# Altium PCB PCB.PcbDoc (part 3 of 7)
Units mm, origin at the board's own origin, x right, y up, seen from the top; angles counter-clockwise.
Board outline 243.2 x 142.8 mm, 4 copper layers (Top Layer, Layer 1, Layer 2, Bottom Layer), stack 0.603 mm thick; 451 components, 380 nets, 2276 pads, 1520 vias.
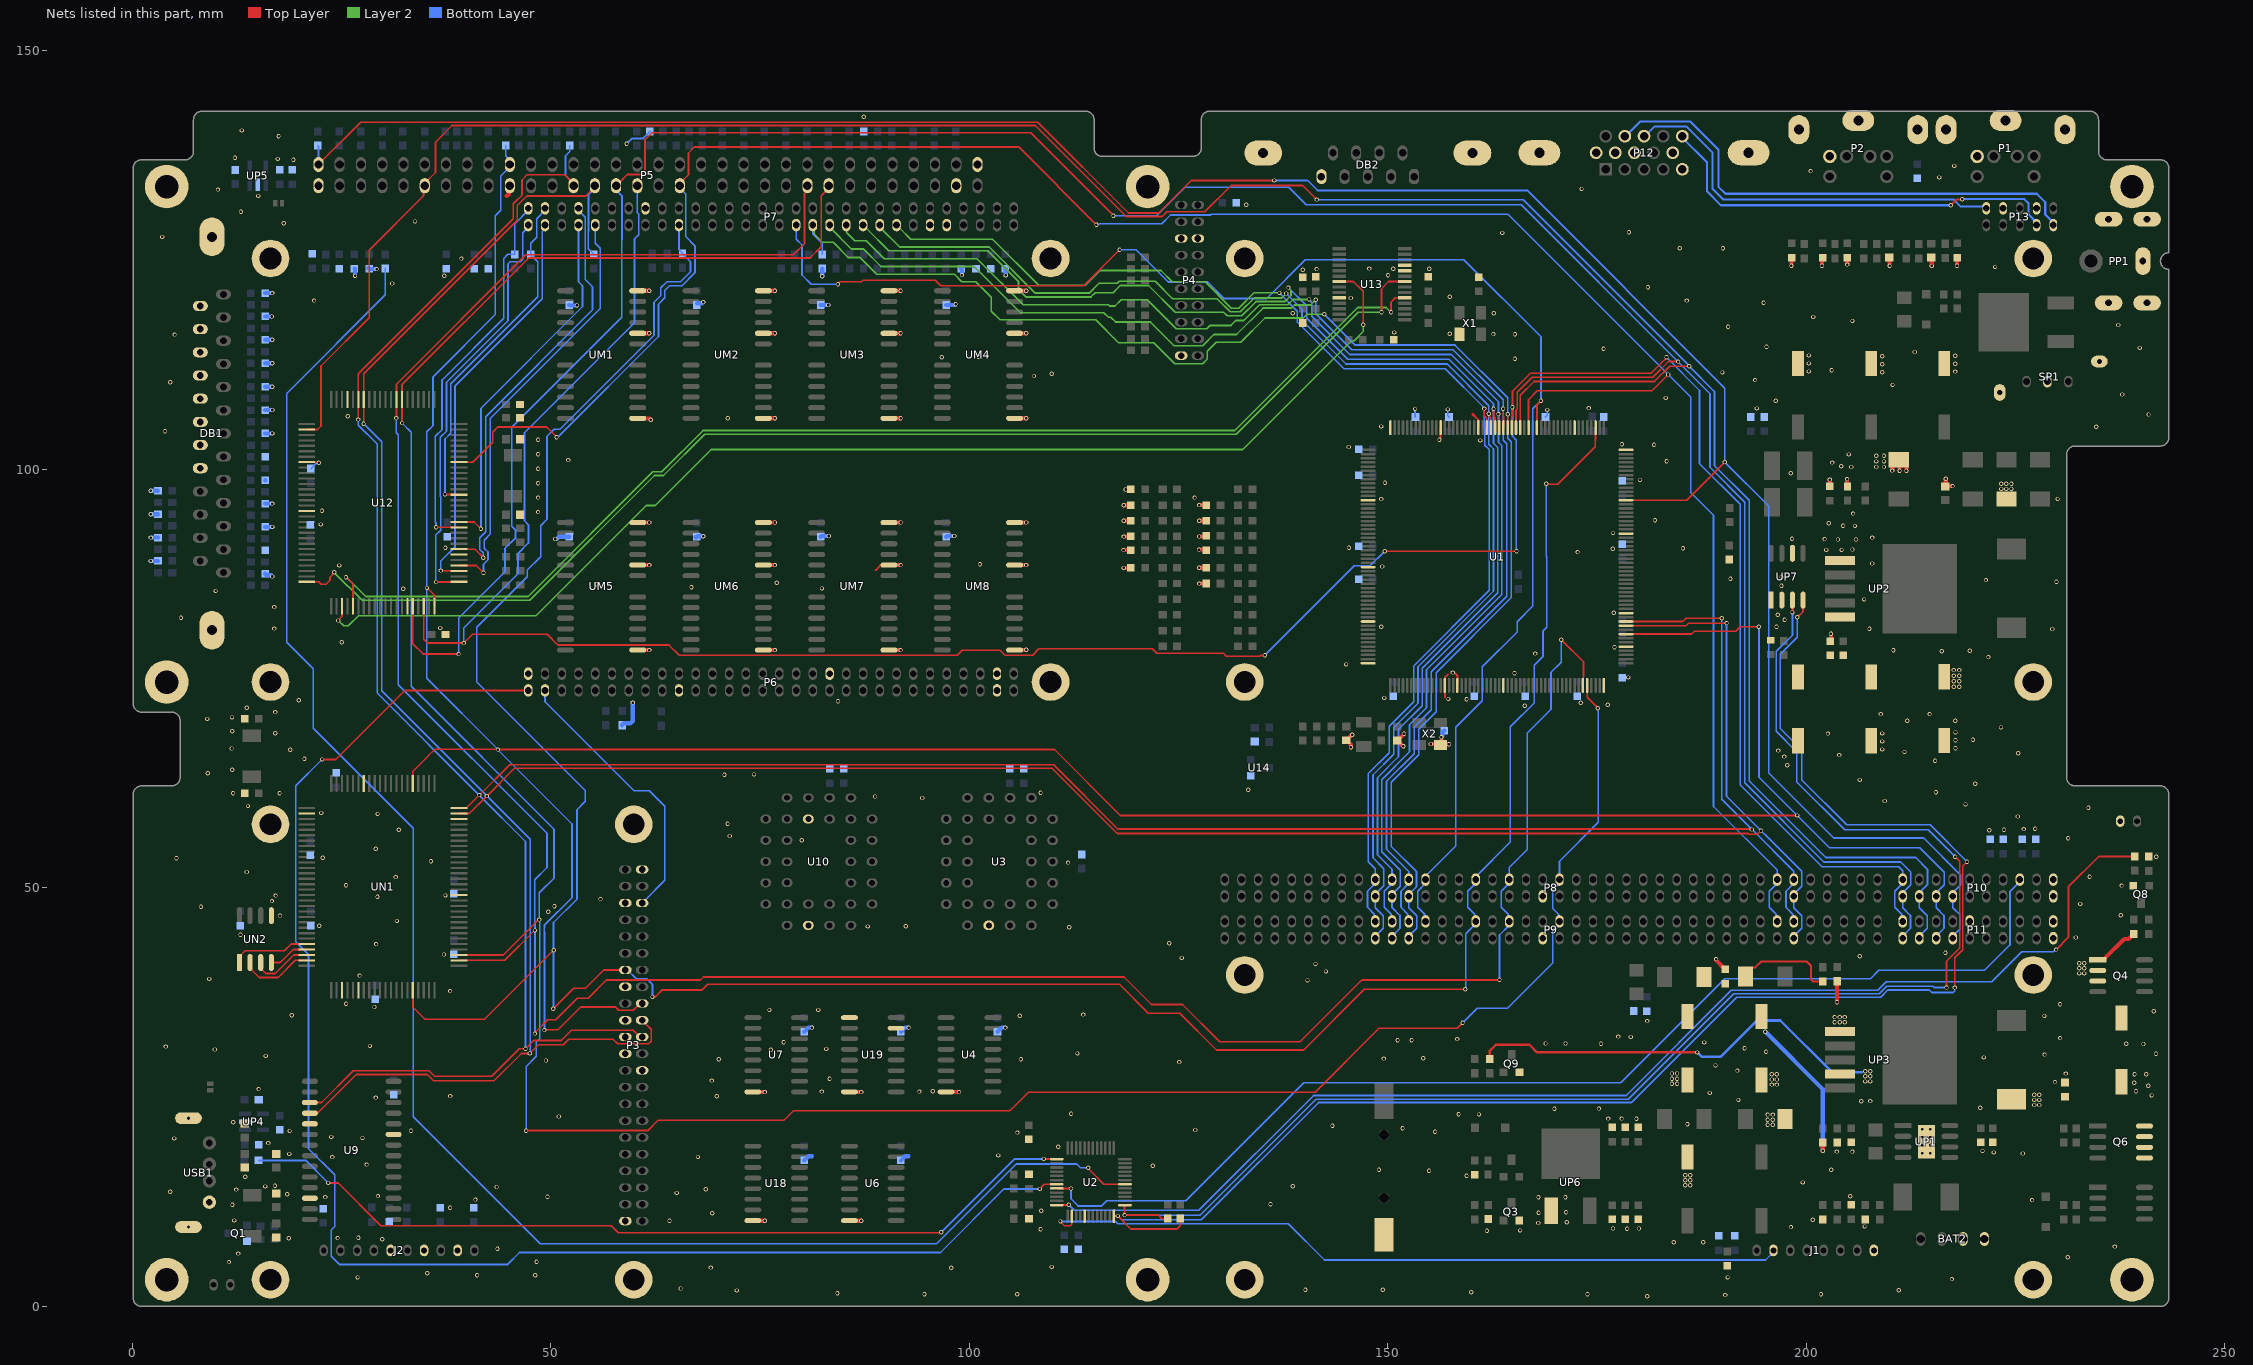
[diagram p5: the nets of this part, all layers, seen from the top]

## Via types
v1: diameter 0.508, hole 0.305, Top Layer to Bottom Layer, tented both sides, 1451 vias
v2: diameter 0.508, hole 0.3, Top Layer to Bottom Layer, 67 vias
v3: diameter 1.2, hole 1.2, Top Layer to Bottom Layer, 2 vias

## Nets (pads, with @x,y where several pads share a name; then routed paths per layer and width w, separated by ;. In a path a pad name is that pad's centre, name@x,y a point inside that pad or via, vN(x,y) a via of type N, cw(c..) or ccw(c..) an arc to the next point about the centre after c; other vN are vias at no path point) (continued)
DACK3#: P5.29 P10.20 P11.20 U1.22 U12.96 | length 333
  Top Layer w0.203: U12.96@33.501,83.654 33.501,79.191 34.728,77.964 38.954,77.964 v1(38.975,77.943) ; P5.29@57.79,133.9 57.79,133.93 58.25,134.391 58.281,134.391 59.125,135.235 60.705,135.235 61.251,135.781 61.251,139.411 62.08,140.241 107.34,140.241 117.205,130.376 v1(117.205,130.316) ; U1.22@165.305,104.994 165.305,107.064 165.441,107.201 165.441,109.206 167.241,111.006 181.635,111.006 183.522,112.893 v1(184.669,112.893)
  Bottom Layer w0.203: v1(38.975,77.943) 38.975,82.261 43.852,87.138 43.857,87.138 44.512,87.792 44.512,90.567 45.782,91.837 45.782,92.751 45.312,93.221 45.312,105.029 58.464,118.181 58.464,127.45 58.486,127.471 58.486,132.704 57.79,133.4 P5.29@57.79,133.9 ; v1(117.205,130.316) 117.207,130.318 122.363,130.318 125.767,133.721 138.136,133.721 140.242,131.616 165.921,131.616 184.644,112.893 v1(184.669,112.893) ; v1@184.656,112.881 188.477,109.06 188.477,100.248 192.643,96.082 192.643,62.552 202.088,53.107 211.258,53.107 212.457,51.908 212.457,50.384 211.5,49.427 P10.20@211.5,49 211.5,47.638 212.437,46.701 212.437,45.187 211.5,44.25 P11.20@211.5,44
DACK5#: P7.35 P8.58 P9.58 R22.2 U1.24 | length 177
  Top Layer w0.203: U1.24@164.305,104.994 164.314,105.003 164.314,106.584 v1(164.324,106.594)
  Layer 2 w0.203: P7.35@81.3,129.2 81.432,129.068 81.432,128.145 82.434,127.143 83.73,127.143 85.558,125.314 86.946,125.314 88.938,123.322 98.218,123.322 99.097,122.444 100.748,122.444 102.602,120.589 102.602,118.92 103.65,117.872 115.094,117.872 117.812,115.154 122.033,115.154 124.547,112.639 127.875,112.639 128.435,113.2 128.435,114.14 129.5,115.205 132.421,115.205 135.317,118.1 139.889,118.1 140.341,118.552 v1(142.404,118.552)
  Bottom Layer w0.203: P7.35@81.3,129.2 81.3,128.15 82.425,127.025 R22.2@82.425,125.7 ; v1(142.404,118.552) 146.097,114.859 158.014,114.859 164.324,108.549 v1(164.324,106.594) 164.324,103.722 164.754,103.292 164.754,84.701 155.764,75.711 155.764,71.043 153.677,68.956 153.677,65.919 150.405,62.647 150.405,54.956 153.427,51.933 153.427,50.177 152.5,49.25 P8.58@152.5,49 152.5,47.638 153.437,46.701 153.437,45.187 P9.58@152.5,44.25
DACK6#: P7.39 P8.60 P9.60 U1.26 | length 165.6
  Top Layer w0.203: v1(163.206,106.619) 163.206,106.537 163.305,106.439 U1.26@163.305,104.994
  Layer 2 w0.203: P7.39@85.3,129.2 85.361,129.139 85.361,128.28 86.315,127.326 87.687,127.326 89.827,125.185 100.915,125.185 106.434,119.666 116.606,119.666 116.75,119.523 117.387,119.523 118.124,120.259 121.253,120.259 124.717,116.795 128.373,116.795 128.789,117.211 131.253,117.211 131.837,117.795 132.777,117.795 134.657,119.675 138.035,119.675 138.67,120.31 v1(140.575,120.31)
  Bottom Layer w0.203: v1(140.575,120.31) 140.888,119.997 140.888,118.315 145.461,113.742 157.551,113.742 163.206,108.086 v1(163.206,106.619) 163.206,103.265 163.611,102.86 163.611,85.07 154.621,76.079 154.621,71.517 152.589,69.485 152.589,66.259 149.262,62.931 149.262,54.346 151.471,52.136 151.471,50.221 150.5,49.25 P8.60@150.5,49 150.5,47.638 151.437,46.701 151.437,45.187 150.5,44.25 P9.60@150.5,44
DACK7#: P7.43 P8.62 P9.62 U1.28 | length 159.1
  Top Layer w0.203: v1(162.063,106.645) 162.122,106.586 162.122,106.339 162.305,106.156 U1.28@162.305,104.994
  Layer 2 w0.203: P7.43@89.3,129.2 89.3,128.95 91.667,126.583 102.374,126.583 107.886,121.071 114.31,121.071 115.48,122.24 117.664,122.24 117.893,122.469 122.211,122.469 124.275,120.405 129.583,120.405 131.151,118.837 132.371,118.837 134.022,120.488 137.324,120.488 v1(137.857,121.021)
  Bottom Layer w0.203: v1(137.857,121.021) 139.745,119.133 139.745,117.841 144.987,112.599 157.077,112.599 162.063,107.613 v1(162.063,106.645) 162.063,103.013 162.626,102.45 162.626,85.478 153.591,76.443 153.591,72.062 150.709,69.18 150.709,65.979 148.22,63.49 148.22,53.61 149.516,52.314 149.516,50.266 P8.62@148.5,49.25 ; P9.62@148.5,44 148.5,44.25 149.437,45.187 149.437,46.701 148.5,47.638 P8.62@148.5,49.25 ; P8.62@148.5,49 P8.62@148.5,49.25
DCD1#: U12.85 U13.19 | length 147.2
  Top Layer w0.203: v1(25.513,87.133) 25.577,87.133 26.351,86.36 U12.85@26.351,83.654 ; v1(150.379,118.786) 150.379,119.984 150.895,120.5 U13.19@152,120.5
  Layer 2 w0.203: v1(25.513,87.133) 25.568,87.133 27.875,84.826 47.281,84.826 62.19,99.736 63.257,99.736 68.185,104.664 131.705,104.664 146.387,119.345 149.82,119.345 v1(150.379,118.786)
DCDC12V: C26.1 CP6.1 CP8.1 DP7.K DP10.A R88.1 R114.1 | length 30.1
  Top Layer w0.254: DP7.K@192.721,39.436 192.721,39.736 193.494,40.509 193.896,40.509 194.601,41.214 200.036,41.214 200.544,40.706 200.544,39.081 200.798,38.827 R88.1@201.967,38.827
  Top Layer w0.508: v1(201.941,18.608) 201.941,19.548 R114.1@201.967,19.574
  Bottom Layer w0.508: v1(195.083,32.832) 201.941,25.974 v1(201.941,18.608)
DDCSCK: P12.12 P13.9 | length 60.7
  Bottom Layer w0.254: P12.12@178.31,139.72 180.16,141.57 186.142,141.57 189.478,138.234 189.478,133.789 190.333,132.934 227.519,132.934 228.535,131.918 228.535,130.465 229.5,129.5 P13.9@229.5,129.2
DDCSDA: P12.15 P13.7 | length 50.3
  Top Layer w0.254: v1(217.257,131.562) 217.969,132.273 v1(218.629,132.273)
  Bottom Layer w0.254: P12.15@185.18,139.72 185.18,139.637 188.124,136.693 188.124,133.228 189.783,131.569 217.251,131.569 v1(217.257,131.562) ; v1(218.629,132.273) 218.654,132.299 226.046,132.299 226.528,131.816 226.528,130.472 227.5,129.5 P13.7@227.5,129.2
DENSEL#: P7.1 U12.1 | length 50.7
  Top Layer w0.203: v1(36.282,86.553) 36.285,86.551 38.997,86.551 U12.1@39.026,86.579
  Bottom Layer w0.203: v1(36.282,86.553) 36.257,86.579 36.257,92.167 36.841,92.751 36.841,96.736 36.79,96.787 36.79,103.837 37.519,104.566 37.519,110.422 44.868,117.77 44.868,124.552 45.122,124.806 46.341,124.806 46.62,125.085 46.62,128.27 47.3,128.95 P7.1@47.3,129.2
DIR#: P7.8 U12.7 | length 51.6
  Top Layer w0.203: U12.7@39.026,90.479 40.942,90.479 41.921,89.5 v1(41.921,89.448)
  Bottom Layer w0.203: v1(41.921,89.448) 41.921,90.033 41.515,90.44 41.515,91.862 42.201,92.548 42.201,106.308 54.977,119.084 54.977,121.809 54.089,122.697 54.089,128.601 54.105,128.617 54.105,130.145 53.3,130.95 P7.8@53.3,131.2
DRQ0: P7.33 P8.55 P9.55 U1.17 | length 184.6
  Top Layer w0.203: v1(84.288,122.139) 84.568,122.418 87.108,122.418 87.286,122.596 95.922,122.596 96.558,121.959 113.646,121.959 117.939,126.252 v1(117.945,126.252) ; U1.17@167.805,104.994 167.805,107.738 168.285,108.218 v1(168.288,108.218)
  Bottom Layer w0.203: P7.33@79.3,129.2 79.3,127.514 79.996,126.818 79.996,123.231 81.088,122.139 v1(84.288,122.139) ; v1(117.945,126.252) 117.948,126.255 119.898,126.255 123.748,122.405 128.472,122.405 130.463,120.414 135.497,120.414 140.145,125.062 159.064,125.062 168.286,115.84 v1(168.288,108.218) ; P9.55@154.384,46.116 154.384,46.865 153.558,47.691 153.558,49.622 P8.55@154.5,50.564 ; P8.55@154.5,51 154.5,51.406 158.103,55.009 158.103,69.182 161.27,72.349 161.27,76.413 165.441,80.584 165.441,81.807 167.321,83.687 167.321,107.254 168.285,108.218 v1(168.288,108.218)
DRQ1: P5.35 P8.13 P9.13 U1.19 U12.23 | length 279.6
  Top Layer w0.203: U12.23@39.026,100.879 40.651,100.879 43.039,103.267 43.039,104.46 43.648,105.07 49.49,105.07 50.683,103.878 v1(50.683,103.852) ; P5.35@65.41,133.9 65.41,134.2 66.432,135.222 66.432,137.811 67.158,138.536 105.89,138.536 v1(115.175,129.251) ; U1.19@166.805,104.994 166.805,108.338 167.854,109.388 181.545,109.388 v1(183.501,111.344)
  Bottom Layer w0.203: v1(50.683,103.852) 50.765,103.852 50.892,103.979 50.94,103.979 62.851,115.89 62.851,119.751 63.597,120.498 63.597,121.387 64.172,121.961 65.67,121.961 67.207,123.498 67.207,126.724 66.105,127.826 66.105,132.905 65.41,133.6 P5.35@65.41,133.9 ; v1(115.175,129.251) 115.233,129.309 115.484,129.309 115.528,129.352 122.973,129.352 124.025,130.405 128.826,130.405 128.914,130.493 139.777,130.493 164.348,130.493 183.499,111.342 186.193,108.649 186.193,97.244 188.904,94.533 188.904,59.737 196.5,52.141 P8.13@196.5,51 ; P9.13@196.5,46 196.384,46.116 196.384,46.865 195.558,47.691 195.558,49.622 P8.13@196.5,50.564
DRQ2: P5.11 P10.18 P11.18 U1.21 U12.52 | length 320.2
  Top Layer w0.203: U12.52@20.826,104.779 22.123,104.779 22.541,105.197 22.541,112.369 28.281,118.109 28.281,126.203 34.774,132.695 34.774,133.744 P5.11@34.93,133.9 34.93,134.2 36.206,135.476 36.206,139.106 38.193,141.093 107.879,141.093 118.751,130.222 123.029,130.222 123.593,130.786 128.14,130.786 131.278,133.924 139.813,133.924 v1(141.489,132.248) ; U1.21@165.805,104.994 165.805,107.025 165.822,107.043 165.822,108.88 167.448,110.506 181.842,110.506 183.67,112.334 185.99,112.334 v1(185.991,112.336)
  Bottom Layer w0.203: v1(141.489,132.248) 141.511,132.227 166.174,132.227 185.991,112.409 v1(185.991,112.336) 189.011,109.316 189.011,100.469 193.177,96.303 193.177,62.774 202.31,53.641 213.054,53.641 214.457,52.238 214.457,50.384 213.5,49.427 P10.18@213.5,49 213.5,47.638 214.437,46.701 214.437,45.187 213.5,44.25 P11.18@213.5,44
DRQ3: P5.31 P10.19 P11.19 U1.23 U12.98 | length 332.8
  Top Layer w0.203: U12.98@34.801,83.654 34.801,79.729 35.266,79.264 v1(39.584,79.264) 40.626,80.305 49.55,80.305 50.826,79.029 64.102,79.029 65.321,77.81 98.536,77.81 99.136,78.41 103.657,78.41 104.258,77.81 107.553,77.81 108.306,78.562 121.845,78.562 122.379,78.029 130.353,78.029 130.704,77.678 134.645,77.678 134.747,77.78 135.276,77.78 v1(135.306,77.81) ; v1(149.617,90.236) v1(165.365,90.236) ; U1.23@164.805,104.994 164.805,106.285 164.883,106.363 v1(164.883,107.432) 164.883,109.354 167.034,111.506 181.427,111.506 183.287,113.365 v1(183.287,113.4)
  Bottom Layer w0.203: v1(39.584,79.264) 39.584,81.067 46.081,87.563 46.081,89.979 47.314,91.212 47.314,93.385 46.844,93.855 46.844,104.394 59.996,117.546 59.996,127.564 60.486,128.054 60.486,130.519 60.33,130.675 P5.31@60.33,133.9 ; v1(135.306,77.81) 145.98,88.484 147.865,88.484 v1(149.617,90.236) ; v1(164.883,107.432) 164.883,103.978 165.352,103.508 165.352,90.249 v1(165.365,90.236) ; v1(183.287,113.4) 183.287,113.386 187.235,109.439 187.235,100.703 192.111,95.826 192.111,62.296 201.858,52.55 211.027,52.55 211.5,52.077 P10.19@211.5,51 ; P11.19@211.384,46.116 211.384,46.865 210.558,47.691 210.558,49.622 P10.19@211.5,50.564
DRQ5: P7.37 P8.57 P9.57 U1.25 | length 166.8
  Top Layer w0.203: v1(163.765,107.254) 163.765,106.363 163.805,106.323 U1.25@163.805,104.994
  Layer 2 w0.203: P7.37@83.3,129.2 83.3,128.95 85.92,126.33 87.367,126.33 89.443,124.254 100.591,124.254 104.558,120.287 104.558,120.285 106.108,118.734 116.065,118.734 116.623,118.176 116.909,118.176 117.468,117.618 121.626,117.618 124.449,114.795 127.883,114.795 129.207,116.119 131.913,116.119 135.088,119.294 138.492,119.294 138.848,119.65 140.753,119.65 v1(141.388,120.285)
  Bottom Layer w0.203: v1(141.388,120.285) 141.388,118.605 145.692,114.301 157.782,114.301 163.765,108.318 v1(163.765,107.254) 163.765,103.495 164.183,103.078 164.183,84.833 155.193,75.843 155.193,71.28 153.148,69.235 153.148,66.056 149.833,62.741 149.833,54.638 152.5,51.971 P8.57@152.5,51 ; P9.57@152.384,46.116 152.384,46.865 151.558,47.691 151.558,49.622 P8.57@152.5,50.564
DRQ6: P7.41 P8.59 P9.59 U1.27 | length 161.8
  Top Layer w0.203: v1(162.622,107.254) 162.622,106.413 162.805,106.231 U1.27@162.805,104.994
  Layer 2 w0.203: P7.41@87.3,129.2 87.3,129.166 87.668,128.798 87.702,128.798 90.383,126.117 102.185,126.117 105.878,122.424 105.878,121.466 106.73,120.615 114.534,120.615 115.042,121.123 117.183,121.123 117.577,121.517 117.577,121.531 118.033,121.986 121.398,121.986 124.589,118.795 130.355,118.795 130.796,118.354 132.548,118.354 134.25,120.056 137.682,120.056 138.416,120.79 138.416,121.345 138.111,121.65 v1(138.111,121.732)
  Bottom Layer w0.203: v1(138.111,121.732) 140.304,119.54 140.304,118.073 145.219,113.158 157.309,113.158 162.622,107.844 v1(162.622,107.254) 162.622,103.14 163.138,102.624 163.138,85.266 154.103,76.231 154.103,71.786 151.268,68.951 151.268,65.7 148.754,63.185 148.754,53.959 150.5,52.213 P8.59@150.5,51 ; P9.59@150.384,46.116 150.384,46.865 149.558,47.691 149.558,49.622 P8.59@150.5,50.564
DRQ7: P7.45 P8.61 P9.61 U1.29 | length 153.7
  Top Layer w0.203: v1(161.504,107.28) 161.504,106.413 161.692,106.225 161.692,106.193 161.805,106.081 U1.29@161.805,104.994
  Layer 2 w0.203: P7.45@91.3,129.2 91.3,129.166 91.668,128.798 91.702,128.798 92.985,127.515 102.76,127.515 108.272,122.003 113.871,122.003 115.632,123.764 122.886,123.764 124.236,122.414 128.158,122.414 131.304,119.269 132.167,119.269 133.996,121.097 v1(137.044,121.097)
  Bottom Layer w0.203: v1(137.044,121.097) 137.044,121.044 139.186,118.902 139.186,117.61 144.756,112.04 156.846,112.04 161.363,107.523 161.363,107.503 161.504,107.362 v1(161.504,107.28) 161.504,105.012 161.582,104.935 161.582,102.912 162.114,102.38 162.114,85.557 153.079,76.522 153.079,72.261 150.151,69.332 150.151,66.157 147.661,63.668 147.661,53.127 148.5,52.288 P8.61@148.5,51 ; P9.61@148.5,46 148.384,46.116 148.384,46.865 147.558,47.691 147.558,49.622 P8.61@148.5,50.564
DS0#: P7.9 U12.4 | length 51.3
  Top Layer w0.203: U12.4@39.026,88.529 41.063,88.529 v1(41.947,87.646)
  Bottom Layer w0.203: v1(41.947,87.646) 41.947,88.663 42.48,89.197 42.48,90.132 42.023,90.589 42.023,91.557 42.759,92.294 42.759,106.086 55.912,119.238 55.912,126.411 55.3,127.023 P7.9@55.3,129.2
DS1#: P7.3 U12.3 | length 48.6
  Top Layer w0.203: v1(36.841,87.925) 36.864,87.902 39.003,87.902 U12.3@39.026,87.879
  Bottom Layer w0.203: v1(36.841,87.925) 36.841,89.068 38.553,90.78 38.553,109.99 48.957,120.394 48.957,128.433 49.3,128.776 P7.3@49.3,129.2
DSKCHG#: P7.4 R137.1 U12.17 | length 41.5
  Top Layer w0.203: v1(37.349,97.018) 37.369,96.999 39.006,96.999 U12.17@39.026,96.979
  Bottom Layer w0.203: v1(37.349,97.018) 37.349,103.648 38.036,104.335 38.036,110.227 48.424,120.615 48.424,124.814 47.576,125.662 R137.1@47.576,125.7 47.576,127.032 48.297,127.752 48.297,129.947 49.3,130.95 P7.4@49.3,131.2
DSR1#: U12.80 U13.22 | length 151
  Top Layer w0.203: U12.80@20.826,86.579 22.274,86.579 22.578,86.274 23.128,86.274 23.601,86.747 23.601,87.128 24.131,87.658 v1(24.131,87.733) ; v1(149.236,118.786) 149.236,121.605 150.081,122.45 U13.22@152,122.45
  Layer 2 w0.203: v1(24.131,87.733) 24.131,87.679 27.442,84.369 47.47,84.369 62.38,99.279 63.447,99.279 68.374,104.206 131.895,104.206 146.474,118.786 v1(149.236,118.786)
DTR1#: U12.83 U13.7 | length 147.3
  Top Layer w0.203: v1(24.598,81.956) 24.598,82.007 25.051,82.459 U12.83@25.051,83.654 ; U13.7@144.2,122.45 145.877,122.45 147.052,121.275 v1(147.052,117.28)
  Layer 2 w0.203: v1(24.598,81.956) 25.233,81.321 25.792,81.321 27.01,82.539 48.228,82.539 61.387,95.697 62.479,95.697 69.159,102.378 132.652,102.378 145.657,115.382 145.96,115.382 147.052,116.475 v1(147.052,117.28)
EECS: UN1.76 UN2.1 | length 9.4
  Top Layer w0.203: UN2.1@12.79,41.1 12.79,41.811 13.463,42.484 18.147,42.484 18.962,43.3 UN1.76@20.826,43.3
EED5: UN1.79 UN2.2 | length 8.8
  Top Layer w0.203: UN2.2@14.06,41.1 14.06,40.389 15.139,39.309 17.436,39.309 19.476,41.35 UN1.79@20.826,41.35
EED6: UN1.78 UN2.3 | length 7.4
  Top Layer w0.203: UN2.3@15.33,41.1 15.33,40.399 15.95,39.779 17.067,39.779 19.288,42 UN1.78@20.826,42
EED7: UN1.77 UN2.4 | length 4.9
  Top Layer w0.203: UN2.4@16.6,41.1 17.651,41.1 19.201,42.65 UN1.77@20.826,42.65
EN_MIO: R144.1 U12.58 | length 2.7
  Top Layer w0.203: U12.58@20.826,100.879 20.854,100.85 22.211,100.85 v1(22.26,100.801)
  Bottom Layer w0.203: R144.1@21.3,100.1 21.338,100.1 21.983,100.744 22.203,100.744 v1(22.26,100.801)
ERR_FLP: P6.1 U2.7 | length 181.8
  Top Layer w0.203: v2(22.657,65.354) 24.308,65.354 32.554,73.6 P6.1@47.3,73.6 ; v1(108.407,14.046) 108.964,14.603 U2.7@110.431,14.603
  Bottom Layer w0.203: v2(22.657,65.354) 19.533,62.23 19.533,43.561 21.031,42.062 21.031,18.872 24.181,15.723 24.181,9.55 23.774,9.144 23.774,6.02 24.79,5.004 44.806,5.004 46.253,6.452 96.545,6.452 104.14,14.046 v1(108.407,14.046)
ERR_ISA: R150.2 U2.30 | length 208.8
  Top Layer w0.203: v1(114.197,16.562) 114.197,16.486 116.066,14.617 118.567,14.617 U2.30@118.581,14.603
  Bottom Layer w0.203: R150.2@30.226,124.005 30.226,120.853 18.44,109.068 18.44,79.348 21.615,76.173 21.615,69.088 33.553,57.15 33.553,22.682 48.743,7.493 96.063,7.493 105.585,17.015 112.827,17.015 113.28,16.562 v1(114.197,16.562)
ERR_USB: R151.2 U2.1 | length 102.6
  Top Layer w0.203: v1(23.393,14.757) 24.587,14.757 29.693,9.652 57.226,9.652 58.064,8.814 96.593,8.814 v1(96.646,8.866) ; v1(108.89,17.628) 108.902,17.615 110.419,17.615 U2.1@110.431,17.603
  Bottom Layer w0.203: R151.2@15.086,17.45 20.701,17.45 v1(23.393,14.757) ; v1(96.646,8.866) 96.648,8.866 105.41,17.628 v1(108.89,17.628)
FAN_SW: R102.1 U2.12 | length 150.1
  Top Layer w0.203: U2.12@110.431,12.103 110.45,12.121 111.842,12.121 v1(111.862,12.141) ; v1(229.83,42.637) 231.304,44.11 231.304,50.13 234.936,53.762 R102.1@239.228,53.762
  Bottom Layer w0.203: v1(111.862,12.141) 112.522,11.481 127.406,11.481 141.122,25.197 178.46,25.197 191.033,37.77 208.534,37.77 209.55,38.786 222.148,38.786 225.73,42.367 229.508,42.367 229.778,42.637 v1(229.83,42.637)
GND: BAT1.2 BAT2.1 BAT2.2 C1.1 C2.2 C3.2 C4.1 C5.2 C6.2 C7.2 C8.2 C9.2 C10.2 C11.1 C12.1 C13.2 C14.2 C15.2 C16.2 C17.2 C18.2 C19.2 C20.2 C21.2 C23.2 C24.2 C25.2 C26.2 C27.2 C28.2 C29.2 C30.2 C31.2 C32.2 C33.1 C34.1 C35.1 C36.2 C37.2 C38.2 C39.2 C40.2 C41.2 C42.2 C43.2 C44.2 C45.2 C46.2 C47.2 C48.2 C49.2 C50.2 C51.2 C52.2 C53.2 C54.2 C55.2 C56.2 C57.2 C58.2 C59.2 C60.2 C61.2 C62.2 C63.2 C64.2 C65.2 C66.2 C67.2 C68.2 C69.2 C70.2 C71.2 C72.2 C73.2 C74.2 C75.2 C76.2 C77.1 C78.1 C79.2 C80.2 C81.2 C82.2 C83.2 C84.2 C85.2 C90.2 C91.2 C99.2 C100.2 C101.2 C102.2 C103.2 C104.2 C105.2 C106.2 C107.2 C108.2 C109.2 C110.2 C111.2 C112.2 C113.2 C114.2 C115.2 C116.2 C117.1 C118.1 C119.2 C120.2 C121.2 C122.2 C126.2 C130.2 C131.2 C132.2 C133.2 C134.2 C135.2 C136.2 C137.2 C138.2 C139.2 C140.2 C141.2 C142.2 C143.2 C144.2 C145.2 C146.2 C147.2 C148.2 C149.2 CM1.2 CM2.2 CM3.2 CM4.2 CM5.2 CM6.2 CM7.2 CM8.2 CM9.2 CM10.2 CM11.2 CM12.2 CN1.2 CN2.2 CN3.2 CN4.2 CN5.2 CP1.1 CP2.2 CP3.2 CP4.2 CP5.2 CP6.2 CP8.2 CP9.2 CP10.2 CP11.2 CP12.1 DB1.0 DB1.18 DB1.19 DB1.20 DB1.21 DB1.22 DB1.23 DB1.24 DB1.25 DB2.0 DB2.5 DP6.A DP8.K J1.1 J2.2 J2.4 J2.6 LED2.2 M1.1 M2.1 M3.1 M4.1 M5.1 M6.1 M7.1 P1.3 P1.7 P2.3 P2.7 P3.2 P3.19 P3.22 P3.24 P3.26 P3.30 P3.40 P3.43 P4.2 P4.15 P4.16 P5.1 P5.19 P5.61 P5.64 P6.2 P6.19 P6.38 P6.57 P6.58 P7.16 P7.49 P7.51 P8.42 P9.42 P10.1 P10.2 P11.1 P11.2 P12.0 P12.5 P12.6 P12.7 P12.8 P12.10 P13.4 P13.8 PP1.2 PP1.3 PP2.1 Q1.E Q3.E Q8.E Q9.E R7.1 R22.1 R23.1 R24.1 R25.1 R26.2 R89.2 R97.2 R103.2 R111.2 R113.1 R115.1 R116.1 R117.1 R145.2 R146.2 R147.2 RT1.2 SP1.0 SP1.2 T1.1 T2.1 T3.1 T4.1 T5.1 T6.1 T7.1 T8.1 T11.1 T12.1 T13.1 T14.1 T15.1 T16.1 T17.1 T18.1 U1.8 U1.31 U1.40 U1.52 U1.65 U1.81 U1.94 U1.104 U1.118 U1.121 U1.132 U1.156 U1.161 U1.169 U1.188 U1.208 U2.17 U3.16 U4.8 U6.8 U7.8 U9.5 U9.12 U9.23 U10.3 U10.16 U12.6 U12.47 U12.67 U12.95 U13.10 U13.24 U13.25 U14.1 U18.8 U19.1 U19.8 U19.15 UM1.13 UM1.20 UM1.24 UM2.13 UM2.20 UM2.24 UM3.13 UM3.20 UM3.24 UM4.13 UM4.20 UM4.24 UM5.13 UM5.20 UM5.24 UM6.13 UM6.20 UM6.24 UM7.13 UM7.20 UM7.24 UM8.13 UM8.20 UM8.24 UN1.14 UN1.28 UN1.44 UN1.52 UN1.83 UN1.86 UN2.5 UP1.0 UP2.1 UP3.1 UP4.2 UP5.2 UP6.1 UP7.1 UP7.2 UP7.6 USB1.0 USB1.GND X1.2 X2.2 | length 127
  Top Layer w0.254: 88.81,87.976 89.345,88.511 90.324,88.511 UM7.20@90.392,88.579 ; v1(156.159,103.546) 156.159,103.615 156.305,103.76 U1.40@156.305,104.994 ; 156.805,72.787 U1.118@156.805,74.206 156.813,74.215 156.813,75.144 157.161,75.491 ; 158.05,75.631 158.305,75.377 U1.121@158.305,74.206 ; 160.108,106.619 160.796,105.932 160.796,105.003 U1.31@160.805,104.994
  Top Layer w0.508: 44.729,132.664 44.958,132.892 44.958,133.768 P5.19@45.09,133.9 ; UM5.13@60.377,78.421 v1(61.759,78.421) ; UM5.20@60.377,88.581 v1(61.759,88.581) ; UM5.24@60.377,93.661 v1(61.759,93.661) ; UM1.13@60.377,106.111 60.398,106.09 61.78,106.09 v1(61.925,105.945) ; UM1.20@60.377,116.271 v1(61.759,116.271) ; UM1.24@60.377,121.351 v1(61.759,121.351) ; U7.8@74.128,25.63 74.138,25.62 75.549,25.62 v1(75.551,25.619) ; U18.8@74.138,10.253 75.549,10.253 v1(75.551,10.252) ; UM6.13@75.385,78.421 v1(76.767,78.421) ; UM6.20@75.385,88.581 v1(76.767,88.581) ; UM6.24@75.385,93.661 v1(76.767,93.661) ; UM2.13@75.385,106.111 v1(76.767,106.111) ; UM2.20@75.385,116.271 75.388,116.268 v1(76.77,116.268) ; UM2.24@75.385,121.351 v1(76.767,121.351) ; U6.8@85.67,10.263 85.68,10.253 87.091,10.253 v1(87.093,10.252) ; U19.8@85.67,25.63 85.68,25.62 87.091,25.62 v1(87.093,25.619) ; UM7.13@90.392,78.419 v1(91.775,78.421) ; UM7.20@90.392,88.579 v1(91.775,88.581) ; UM7.24@90.392,93.659 v1(91.775,93.661) ; UM3.13@90.394,106.111 v1(91.775,106.111) ; UM3.20@90.394,116.271 v1(91.775,116.271) ; UM3.24@90.394,121.351 v1(91.775,121.351) ; U4.8@97.212,25.63 97.222,25.62 98.755,25.62 v1(98.756,25.619) ; UM8.13@105.402,78.421 105.419,78.439 106.776,78.439 v1(106.783,78.446) ; UM8.20@105.402,88.581 v1(106.783,88.581) ; UM8.24@105.402,93.661 v1(106.783,93.661) ; UM4.13@105.402,106.111 v1(106.783,106.111) ; UM4.20@105.402,116.271 v1(106.783,116.271) ; UM4.24@105.402,121.351 v1(106.783,121.351) ; v1(118.415,90.373) 119.084,90.373 119.3,90.157 CM8.2@119.3,90.152 ; v1(118.453,88.233) 119.282,88.233 CM6.2@119.3,88.251 ; v1(118.453,91.986) 119.282,91.986 CM10.2@119.3,92.004 ; v1(118.453,93.861) 119.282,93.861 CM12.2@119.3,93.879 ; v1(118.453,95.736) 119.282,95.736 CM2.2@119.3,95.754 ; v1(118.664,97.609) 119.282,97.609 CM4.2@119.3,97.627 ; v1(127.432,90.424) 128.076,90.424 128.309,90.191 CM9.2@128.309,90.152 ; v1(127.462,86.368) 128.291,86.368 CM5.2@128.3,86.377 CM5.2@128.309,86.386 ; v1(127.462,88.243) 128.291,88.243 CM7.2@128.3,88.252 CM7.2@128.309,88.261 ; v1(127.462,91.993) 128.291,91.993 CM11.2@128.309,92.011 ; v1(127.462,93.868) 128.291,93.868 CM1.2@128.3,93.877 CM1.2@128.309,93.886 ; v1(127.462,95.743) 128.291,95.743 CM3.2@128.3,95.752 CM3.2@128.309,95.761 ; C3.2@145.013,67.655 145.051,67.655 145.579,67.127 v1(145.579,66.818) ; C3.2@145.068,67.667 145.068,67.672 145.687,68.291 v1(145.731,68.291) ; C4.1@151.113,67.605 151.151,67.605 151.837,66.919 v1(151.852,66.919) ; C4.1@151.24,67.718 151.926,68.404 v1(151.926,68.419) ; v1(155.129,67.199) 155.852,67.199 X2.2@155.981,67.069 ; X2.2@156.283,67.105 156.399,67.221 v1(156.399,68.011) ; X2.2@156.348,67.055 156.476,67.183 v1(157.302,67.183) ; v1(189.205,41.504) 189.205,41.376 C26.2@190.308,40.273 ; v1(198.207,124.323) C8.2@198.207,125.163 ; v1(201.865,124.323) C7.2@201.865,125.163 ; v1(202.779,98.796) 202.779,98.007 C28.2@202.805,97.982 ; C23.2@202.856,79.49 202.932,79.567 v1(202.932,80.381) ; v1(203.657,36.347) 203.657,38.849 R89.2@203.662,38.854 ; v1(204.862,98.847) 204.862,98.031 R111.2@204.912,97.982 ; v1(204.888,124.476) C18.2@204.888,125.316 ; v1(209.942,124.347) C6.2@209.942,125.187 ; v1(210.247,99.863) 210.247,100.512 210.893,101.158 DP6.A@211.034,101.158 ; v1(211.138,99.857) DP6.A@211.138,100.506 ; v1(211.951,99.857) DP6.A@211.951,100.506 ; v1(214.971,124.321) C5.2@214.971,125.161 ; C24.2@216.646,98.229 v1(216.646,98.879) ; C24.2@216.818,98.011 v1(217.467,98.011) ; v1(217.994,124.347) C17.2@217.994,125.187
  Bottom Layer w0.203: v1(153.246,107.229) 153.246,106.321 C41.2@153.3,106.267 ; v1(157.161,107.178) 157.161,106.406 C44.2@157.3,106.267 ; C59.2@168.831,106.267 169.032,106.469 v1(169.032,107.115)
  Bottom Layer w0.254: v1(59.041,138.903) 59.701,139.563 61.026,139.563 61.825,140.362 R25.1@61.825,140.4
  Bottom Layer w0.508: v1(2.196,89.068) C101.2@3.061,89.068 ; v1(2.196,91.862) C102.2@3.061,91.862 ; v1(2.196,94.656) C103.2@3.061,94.656 ; v1(2.196,97.45) C104.2@3.061,97.45 ; C100.2@15.859,87.544 16.055,87.348 16.59,87.348 v1(16.724,87.214) ; C110.2@15.859,93.132 v1(16.724,93.132) ; C111.2@15.859,95.926 v1(16.724,95.926) ; C112.2@15.859,98.72 C112.2@15.911,98.668 ; C114.2@15.859,104.308 v1(16.724,104.308) ; C115.2@15.859,107.102 v1(16.724,107.102) ; C116.2@15.859,109.896 v1(16.724,109.896) ; C105.2@15.859,112.69 v1(16.724,112.69) ; C106.2@15.859,115.484 v1(16.724,115.484) ; C107.2@15.859,118.278 v1(16.661,118.278) ; C108.2@15.859,121.072 v1(16.724,121.072) ; C35.1@26.554,123.993 26.605,123.942 v1(26.605,123.128) ; C34.1@28.154,124.055 28.267,123.942 v1(29.17,123.942) ; v1(50.529,91.695) 50.725,91.695 50.988,91.958 C149.2@52.199,91.958 ; C136.2@52.2,119.65 52.251,119.599 v1(53.121,119.599) ; R26.2@58.507,69.436 58.507,69.474 58.698,69.664 59.48,69.664 59.777,69.962 v1(59.777,72.152) ; C148.2@67.278,91.887 67.365,91.887 C148.2@67.437,91.959 67.508,92.03 v1(68.2,92.03) ; C135.2@67.492,119.846 68.061,119.846 v1(68.217,120.001) ; C40.2@80.275,17.442 80.783,17.95 81.187,17.95 ; C45.2@80.275,32.809 80.783,33.317 v1(81.187,33.317) ; C141.2@82.217,91.959 C141.2@82.217,91.959 82.306,92.049 v1(83.19,92.049) ; C144.2@82.217,119.65 v1(83.136,119.649) ; v1(82.414,123.079) R22.1@82.414,123.99 ; C36.2@91.817,17.442 92.325,17.95 92.726,17.95 92.729,17.948 ; C38.2@91.817,32.809 92.325,33.317 v1(92.728,33.317) ; C140.2@97.225,91.959 C140.2@97.225,91.959 97.315,92.049 v1(98.198,92.049) ; C142.2@97.225,119.65 98.257,119.649 v1(98.349,119.74) ; C139.2@99.024,123.99 99.107,123.906 v1(99.107,123.223) ; C39.2@103.359,32.809 103.867,33.317 104.268,33.317 v1(104.27,33.315) ; C20.2@104.289,123.99 104.331,123.948 v1(104.331,123.181) ; v1(156.399,68.011) 156.531,68.144 156.531,68.603 C62.2@156.727,68.799
  other v1: 180.986,1.209 190.308,1.362 94.626,1.463 105.726,1.463 173.849,1.463 201.738,1.463 84.238,1.565 159.955,1.692 72.198,1.921 211.034,1.946 140.143,1.997 149.389,1.997 65.492,2.149 217.384,3.267 26.91,3.47 190.587,3.47 41.185,3.724 48.144,3.724 35.216,3.978 109.83,4.724 11.532,5.309 231.227,5.883 12.649,6.325 236.841,7.153 184.161,7.674 187.666,7.674 29.845,8.026 18.68,8.144 161.835,9.033 165.797,9.083 178.573,9.287 176.897,9.312 179.996,9.312 198.157,9.49 206.945,9.566 167.956,9.972 171.36,10.049 64.172,10.252 12.178,10.277 200.747,10.353 69.266,11.125 168.007,11.192 171.283,11.242 37.959,11.801 11.949,12.157 135.977,12.208 226.96,12.716 40.981,12.766 167.981,13.046 171.207,13.046 23.049,13.071 49.592,13.097 205.243,13.173 29.335,13.194 18.502,13.401 65.049,13.564 4.532,13.706 12.406,13.96 68.515,13.995 43.51,14.275 15.886,14.341 138.619,14.367 17.029,14.417 185.512,14.47 186.122,14.47 199.579,14.824 185.512,15.08 186.122,15.08 13.473,15.484 159.396,15.611 185.512,15.69 186.122,15.69 154.926,16.221 148.931,16.348 202.983,16.348 121.918,16.826 27.977,16.957 23.887,17.846 67.562,17.868 103.452,18.045 18.731,18.227 225.843,18.278 213.854,18.292 214.814,18.292 222.388,18.405 203.618,18.507 205.497,18.507 221.042,18.583 213.854,19.253 214.814,19.253 16.242,19.523 4.99,20.082 27.494,20.132 213.854,20.213 214.814,20.213 23.76,20.259 155.637,20.869 18.782,20.971 33.285,20.996 126.975,21.082 213.854,21.174 214.814,21.174 151.751,21.301 143.369,21.606 195.367,21.709 195.977,21.709 185.787,21.758 12.051,22.012 195.367,22.319 195.977,22.319 179.691,22.418 176.338,22.444 177.913,22.444 50.95,22.694 195.367,22.929 195.977,22.929 169.901,23.622 175.209,23.647 191.883,24.679 29.069,24.958 37.971,25.132 69.81,25.121 241.235,25.212 188.454,25.517 82.372,25.679 94.031,25.679 239.381,25.72 15.073,25.974 240.854,26.355 195.85,26.51 196.46,26.51 183.937,26.612 184.547,26.612 239.178,26.736 229.703,26.813 69.226,26.99 195.85,27.12 196.46,27.12 83.298,27.219 183.937,27.221 184.547,27.221 195.85,27.729 196.46,27.729 239.203,27.752 240.6,27.752 183.937,27.831 184.547,27.831 230.973,27.829 191.756,28.184 189.14,28.794 125.067,29.196 49.403,29.388 70.064,29.53 106.158,29.53 149.504,29.616 221.194,29.759 15.937,29.937 228.459,30.089 241.768,30.191 112.903,30.226 195.185,30.419 76.276,30.673 9.841,30.699 82.891,30.775 192.619,30.851 3.999,31.054 28.383,31.131 240.27,31.359 238.212,31.385 175.463,31.394 168.834,31.42 171.221,31.42 77.798,31.558 230.313,32.07 179.005,32.197 177.532,32.248 203.366,33.971 203.975,33.971 204.585,33.971 180.986,34.102 203.366,34.58 203.975,34.58 204.585,34.58 228.433,34.712 19.036,34.788 241.514,35.271 76.11,35.433 81.952,35.433 28.916,35.779 230.313,36.109 25.527,36.17 37.959,37.684 140.397,38.954 9.181,39.132 27.138,39.538 142.595,40.033 141.351,40.919 125.386,41.646 206.386,41.849 37.222,42.053 29.12,43.297 123.887,43.399 232.167,44.085 12.914,44.415 111.924,45.304 87.856,45.401 92.403,45.427 22.327,45.491 31.609,46.066 17.639,46.701 237.552,46.726 49.682,47.168 8.19,47.768 50.419,47.803 232.726,48.098 16.674,48.428 55.928,48.678 29.272,48.936 17.105,49.088 37.4,49.114 237.654,50.282 31.456,51.298 13.676,51.908 111.785,53.035 35.673,53.178 5.269,53.559 22.744,53.61 241.794,53.737 29.069,54.676 79.982,55.714 71.374,56.21 221.855,56.886 31.812,56.962 223.607,56.962 225.97,57.039 227.316,57.064 71.106,57.658 225.258,58.537 29.297,58.842 22.566,58.969 233.691,59.579 13.803,59.807 219.01,59.985 209.358,60.391 94.372,60.747 88.733,60.925 12.025,61.306 17.588,61.306 108.509,61.366 215.479,61.433 133.325,61.747 220.178,62.449 206.386,62.906 70.737,63.511 74.267,63.562 9.003,63.693 11.924,64.125 197.725,64.659 215.378,65.192 20.56,65.446 197.344,65.7 203.922,65.878 225.309,66.081 211.72,66.259 196.633,66.411 18.858,66.513 209.049,66.556 11.848,66.665 217.812,66.683 209.049,67.508 217.812,67.635 219.899,67.707 202.576,68.443 209.049,68.461 17.08,68.494 217.812,68.588 11.924,68.723 223.252,69.18 212.05,69.993 217.791,69.993 8.952,70.196 11.898,70.374 208.875,70.78 214.717,70.78 17.055,71.009 13.676,71.542 166.363,71.771 176.262,71.898 173.037,72.128 84.3,72.3 19.863,72.441 159.396,72.533 157.237,72.59 149.566,72.71 178.726,75.149 165.125,75.667 157.745,75.733 145.006,76.712 221.753,77.587 216.165,78.273 219.518,78.349 210.399,78.4 177.075,78.771 25.005,79.365 229.373,80.94 207.529,80.965 16.942,80.991 36.79,81.065 149.211,81.194 196.429,81.194 197.395,82.032 5.802,82.286 196.582,82.642 176.998,82.87 16.942,83.556 206.894,84.471 9.943,85.487 32.371,85.741 82.383,85.791 66.788,85.918 197.014,86.096 55.434,86.299 76.999,86.477 229.881,86.579 221.448,86.782 190.918,86.934 197.014,87.112 149.312,88.408 24.7,88.535 101.256,88.671 207.859,88.763 172.667,90.131 202.373,90.389 204.202,90.389 205.497,90.44 176.871,90.516 185.253,90.592 37.4,90.643 145.35,90.643 203.77,91.633 205.929,91.633 202.17,91.684 198.284,91.735 207.859,91.862 176.897,92.421 205.802,93.259 204.38,93.284 22.49,93.437 202.678,93.564 181.901,93.945 205.573,94.732 48.474,94.91 22.643,95.062 149.211,96.459 230.008,96.485 48.474,96.637 126.898,96.647 48.474,98.364 149.643,98.415 180.123,98.745 198.118,99.554 48.474,100.092 205.345,100.295 208.347,100.293 209.261,100.293 204.151,100.396 203.084,100.828 208.347,100.959 209.261,100.959 183.298,100.981 52.086,101.119 208.347,101.626 209.261,101.626 205.065,101.793 48.474,101.819 145.325,102.682 181.799,102.962 177.964,103.013 161.023,103.471 48.474,103.546 3.897,104.562 234.631,105.095 149.211,105.146 71.143,106.133 25.741,106.365 240.879,106.569 194.056,107.29 174.001,107.331 196.328,108.22 183.208,108.546 237.73,108.956 210.298,110.099 4.532,110.429 193.864,110.683 107.707,111.166 109.841,111.445 189.964,111.594 209.075,111.616 217.787,111.692 200.286,111.717 203.008,111.852 209.075,112.568 217.787,112.644 200.286,112.67 165.176,113.233 96.709,113.401 101.092,113.462 209.075,113.521 217.787,113.597 200.286,113.622 212.939,114.036 175.77,114.436 239.813,114.519 195.236,114.671 5.04,116.119 165.176,116.154 150.759,116.373 190.638,117.059 237.273,117.262 205.497,117.745 200.824,118.227 138.619,118.659 194.88,119.929 21.703,120.183 185.711,120.183 145.553,120.488 181.062,121.758 31.05,122.215 37.246,123.131 150.024,123.206 139.838,123.866 141.483,123.936 150.633,123.968 154.951,123.993 222.541,124.196 39.316,125.201 184.872,126.431 190.029,126.431 3.567,127.778 163.65,128.256 178.802,128.336 18.096,129.429 33.768,129.632 12.965,130.8 133.082,131.638 15.048,132.68 10.222,133.442 173.138,133.518 215.886,134.89 200.493,135.652 217.664,136.261 19.239,136.998 17.359,137.099 12.254,137.252 17.461,139.817 13.067,140.503 87.387,142.154
  other v2: 97.841,4.623 69.088,4.648 48.285,5.334 43.612,6.909 24.511,8.179 27,8.204 108.509,9.22 108.585,11.43 110.617,19.075 105.74,20.777 160.884,22.936 158.445,22.962 112.141,23.012 220.777,23.749 206.553,24.511 207.62,24.536 95.631,25.705 154.229,29.667 187.808,31.547 151.155,31.801 152.832,31.801 158.293,31.953 106.02,34.747 113.589,34.874 216.611,42.266 25.527,50.317 233.832,51.333 231.267,55.931 167.615,78.003 162.611,116.18 157.404,116.205 162.662,118.669 157.378,120.625 147.777,124.003
  other v3: 149.53,12.985 149.53,20.485
HDSEL#: P7.2 R138.1 U12.11 | length 46
  Top Layer w0.203: v1(36.282,93.081) v1(36.282,93.081) 39.024,93.08 U12.11@39.026,93.079
  Bottom Layer w0.203: v1(36.282,93.081) 36.282,93.649 36.19,93.742 36.19,103.967 37.002,104.78 37.002,110.692 44.36,118.049 44.36,125.212 44.847,125.7 R138.1@45.676,125.7 45.676,129.326 47.3,130.95 P7.2@47.3,131.2
HSYNC: P12.13 P13.2 | length 48
  Bottom Layer w0.254: P12.13@180.6,139.72 181.84,140.96 185.687,140.96 188.801,137.846 188.801,133.508 190.058,132.251 217.584,132.251 218.4,131.435 221.265,131.435 P13.2@221.5,131.2
HVOE#: P10.5 U2.8 | length 136.7
  Top Layer w0.203: U2.8@110.431,14.103 110.434,14.1 112.138,14.1 v1(112.141,14.097)
  Bottom Layer w0.203: v1(112.141,14.097) 112.141,12.852 112.979,12.014 115.799,12.014 116.401,12.617 125.856,12.617 139.96,26.721 177.8,26.721 190.246,39.167 207.651,39.167 208.641,40.157 221.28,40.157 224.314,43.191 224.314,49.564 225.5,50.75 P10.5@225.5,51
I2CSCL: R86.1 U2.24 UP7.4 | length 184.9
  Top Layer w0.203: U2.24@117.256,10.778 117.299,10.82 v1(117.729,10.82) 119.304,9.246 124.79,9.246 125.197,9.652 R86.1@125.197,10.49 ; v1(198.919,82.337) 199.604,83.023 UP7.4@199.604,84.394 ; v2(217.729,38.1) 217.729,41.681 218.686,42.638 218.686,52.625 v1(219.188,53.127)
  Bottom Layer w0.203: v1(117.729,10.82) 118.186,10.363 127.711,10.363 141.707,24.359 179.07,24.359 191.668,36.957 208.89,36.957 209.739,37.806 214.695,37.806 214.986,37.516 217.551,37.516 217.729,37.694 v2(217.729,38.1) ; v1(198.919,82.337) 198.919,79.949 196.887,77.917 196.887,69.053 199.452,66.487 199.452,62.906 204.811,57.547 214.794,57.547 219.188,53.152 v1(219.188,53.127)
I2CSDA: R87.1 U2.25 UP7.3 | length 178.8
  Top Layer w0.203: U2.25@118.581,12.103 118.542,12.064 v1(118.542,10.922) 122.555,10.922 122.987,10.49 R87.1@123.723,10.49 ; v1(198.334,82.921) UP7.3@198.334,84.394 ; v2(216.738,38.1) 216.738,41.258 218.305,42.824 218.305,53.197 v1(217.765,53.737)
  Bottom Layer w0.203: v1(118.542,10.922) 118.552,10.912 127.549,10.912 141.402,24.765 178.714,24.765 191.313,37.363 208.712,37.363 209.601,38.252 215.087,38.252 215.24,38.1 v2(216.738,38.1) ; v1(198.334,82.921) 198.334,80.203 196.396,78.265 196.396,68.706 198.859,66.242 198.859,62.66 204.566,56.954 214.548,56.954 v1(217.765,53.737)
IDE1LED#: P3.39 P6.3 | length 33.5
  Bottom Layer w0.203: P6.3@49.3,73.6 49.3,72.24 59.93,61.611 61.759,61.611 63.613,59.756 63.613,50.913 61.302,48.602 61.302,48.568 60.934,48.2 P3.39@60.9,48.2
INDEX#: P7.7 U12.12 | length 44.5
  Top Layer w0.203: U12.12@39.026,93.729 40.816,93.729 v1(41.642,92.903)
  Bottom Layer w0.203: v1(41.642,92.903) 41.642,107.329 53.783,119.471 53.783,121.936 53.3,122.419 P7.7@53.3,129.2
IOCHCK#: P5.2 P10.14 P11.14 R29.1 U1.196 | length 287
  Top Layer w0.203: P5.2@22.23,136.44 22.23,136.47 22.69,136.931 22.721,136.931 27.284,141.494 108.162,141.494 119.007,130.648 122.642,130.648 126.529,134.534 v1(136.409,134.534) ; U1.196@178.463,96.336 185.714,96.336 v1(190.257,100.879)
  Bottom Layer w0.203: R29.1@22.16,138.7 22.23,138.63 P5.2@22.23,136.44 ; v1(136.409,134.534) 140.397,134.534 141.591,133.34 166.635,133.34 190.257,109.718 v1(190.257,100.879) 195.508,95.628 195.508,63.739 203.275,55.972 214.019,55.972 218.457,51.534 218.457,50.384 217.5,49.427 P10.14@217.5,49 217.5,47.638 218.305,46.833 218.305,45.055 P11.14@217.5,44.25
IOCHRDY#: P3.27 P5.20 P10.16 P11.16 R30.1 U1.164 U12.100 UN1.35 | length 375.7
  Top Layer w0.203: UN1.35@33.501,62.475 33.501,63.906 35.444,65.85 35.444,65.881 36.153,66.589 43.626,66.589 v1(43.677,66.538) ; v1(35.19,85.842) 35.216,85.842 36.101,84.957 U12.100@36.101,83.654 ; v1@43.727,66.538 110.17,66.538 118.044,58.664 v1(198.893,58.664) ; v1(49.225,33.02) 49.251,33.045 50.851,33.045 53.594,35.789 57.687,35.789 58.09,35.386 59.836,35.386 60.65,36.2 P3.27@60.9,36.2 ; U1.164@178.463,80.336 186.275,80.336 186.625,80.686 191.553,80.686 192.086,81.219 v1(194.297,81.219)
  Bottom Layer w0.203: R30.1@44.614,138.7 44.614,137.486 45.09,137.01 P5.20@45.09,136.44 45.09,136.14 44.004,135.054 44.004,130.978 43.344,130.318 43.344,118.507 35.927,111.09 35.927,105.248 35.165,104.486 35.165,85.868 v1(35.19,85.842) 35.165,85.817 35.165,75.05 v1(43.677,66.538) 43.677,66.485 52.516,57.645 52.516,48.833 49.225,45.542 49.225,45.291 49.2,45.266 49.2,44.803 49.225,44.777 v1(49.225,33.02) ; v1@194.331,81.219 194.331,64.303 194.331,63.226 v1(198.893,58.664) 202.762,54.795 213.532,54.795 216.457,51.87 216.457,50.384 215.5,49.427 P10.16@215.5,49 215.5,47.638 216.437,46.701 216.437,45.187 215.5,44.25 P11.16@215.5,44
IOCS16#: P3.32 P7.19 P8.49 P9.49 R34.1 U1.3 UN1.96 | length 330.5
  Top Layer w0.203: UN1.96@33.501,37.775 33.501,35.773 34.951,34.322 42.064,34.322 50.312,42.569 v1(50.344,42.569) ; v1(50.293,35.584) 52.721,38.011 54.14,38.011 56.329,40.2 P3.32@58.9,40.2 ; v1(62.128,36.982) 62.187,37.041 62.517,37.041 63.297,37.821 68.097,37.821 68.758,38.481 117.932,38.481 121.387,35.027 125.12,35.027 129.515,30.632 139.929,30.632 147.193,37.897 v1(159.25,37.897) ; v1(168.934,98.288) 168.985,98.237 170.276,98.237 174.77,102.731 174.77,103.447 174.805,103.482 U1.3@174.805,104.994
  Bottom Layer w0.203: v1(50.293,35.584) 50.305,35.596 50.305,42.53 v1(50.344,42.569) ; v1@50.317,42.596 50.317,45.872 53.111,48.666 53.111,59.342 54.113,60.343 54.113,61.647 41.159,74.601 41.159,81.151 47.179,87.171 47.179,87.983 48.779,89.584 48.779,93.284 49.541,94.046 49.541,103.955 50.402,104.816 51.093,104.816 62.317,116.04 62.317,119.98 63.13,120.793 63.13,121.707 63.867,122.444 65.492,122.444 66.686,123.637 66.686,124.798 65.721,125.764 R34.1@65.721,125.802 65.721,125.84 65.3,126.261 P7.19@65.3,129.2 ; P3.32@58.9,40.2 59.15,40.2 60.183,39.167 61.443,39.167 62.128,38.481 v1(62.128,36.982) ; v1(159.25,37.897) 159.305,37.952 159.305,44.516 160.5,45.711 P9.49@160.5,46 ; P9.49@160.384,46.116 160.384,46.865 159.558,47.691 159.558,49.622 P8.49@160.5,50.564 ; P8.49@160.5,51 160.5,51.361 164.629,55.489 164.629,69.246 167.473,72.09 167.473,76.615 168.54,77.682 168.54,80.737 168.972,81.169 168.972,89.561 168.934,89.599 v1(168.934,98.288)
IOKEY: J1.7 U2.14 | length 90.3
  Top Layer w0.203: v1(110.871,10.16) 110.871,10.135 111.358,9.648 112.061,9.648 112.237,9.825 112.237,10.759 U2.14@112.256,10.778
  Bottom Layer w0.203: v1(110.871,10.16) 117.475,10.16 117.739,9.896 138.086,9.896 142.429,5.553 195.12,5.553 196.063,6.496 J1.7@196.063,6.696
IOR#: P3.25 P5.27 P8.12 P9.12 R38.1 U1.166 U9.4 U12.44 UN1.29 | length 400.5
  Top Layer w0.203: U9.4@21.2,23.09 21.283,23.173 22.203,23.173 26.742,27.711 35.209,27.711 35.971,26.949 43.205,26.949 46.482,30.226 v1(47.473,30.226) 48.514,31.267 51.46,31.267 52.121,31.928 57.429,31.928 57.971,31.386 61.663,31.386 61.976,31.699 61.976,33.124 61.302,33.798 61.302,33.832 60.934,34.2 P3.25@60.9,34.2 ; v1(27.621,105.451) 27.636,105.466 27.636,108.339 U12.44@27.651,108.354 27.651,111.424 45.985,129.759 45.985,131.532 47.133,132.68 54.164,132.68 55.25,133.766 P5.27@55.25,133.9 ; UN1.29@39.026,58.9 40.252,58.9 v1(42.326,60.974) 45.647,64.295 109.873,64.295 117.663,56.505 193.025,56.505 193.101,56.429 194.143,56.429 v1(194.575,56.861) ; U1.166@178.463,81.336 185.624,81.336 185.914,81.626 190.435,81.626 v1(190.46,81.651)
  Bottom Layer w0.203: v1(27.621,105.451) 29.78,103.292 29.78,73.577 v1@42.326,61.031 ; v1@42.354,61.002 47.535,55.822 47.535,43.096 47.523,43.085 47.523,30.277 v1(47.473,30.226) ; R38.1@55.1,125.7 55.1,125.738 54.47,126.368 54.47,128.443 54.486,128.459 54.486,132.836 55.25,133.6 P5.27@55.25,133.9 ; v1(190.46,81.651) 190.46,60.975 199.451,51.984 199.451,50.201 198.5,49.25 P8.12@198.5,49 198.5,47.638 199.437,46.701 199.437,45.187 198.5,44.25 P9.12@198.5,44
IOW#: P3.23 P5.25 P8.11 P9.11 R37.1 U1.167 U9.3 U12.45 UN1.30 | length 388.2
  Top Layer w0.203: U9.3@21.2,24.36 22.603,24.36 26.402,28.159 35.444,28.159 36.095,27.508 42.951,27.508 46.228,30.785 v1(46.965,30.785) 47.955,31.775 51.232,31.775 52.461,33.005 59.845,33.005 60.65,32.2 P3.23@60.9,32.2 ; v1(26.986,105.959) 26.993,105.966 26.993,108.347 U12.45@27.001,108.354 27.001,111.435 45.503,129.937 45.503,131.736 46.544,132.777 46.544,134.585 47.154,135.194 51.649,135.194 52.71,134.134 P5.25@52.71,133.9 ; UN1.30@39.026,59.55 39.896,59.55 41.448,61.103 v1(41.464,61.103) 45.081,64.719 110.058,64.719 117.739,57.039 193.432,57.039 v1(193.483,56.988) ; U1.167@178.463,81.836 185.235,81.836 185.634,82.235 v1(189.902,82.235)
  Bottom Layer w0.203: v1(26.986,105.959) 26.986,105.296 29.247,103.035 29.247,73.297 41.453,61.091 41.453,61.057 46.965,55.545 v1(46.965,30.785) ; R37.1@52.252,138.7 52.252,137.981 51.751,137.48 51.751,135.159 52.71,134.2 P5.25@52.71,133.9 ; v1(189.902,82.235) 189.902,60.594 v1@193.483,57.012 ; v1@193.495,57 198.5,51.995 P8.11@198.5,51 ; P9.11@198.384,46.116 198.384,46.865 197.558,47.691 197.558,49.622 P8.11@198.5,50.564
IPSOUT: C22.1 C23.1 C25.1 CP2.1 CP3.1 CP4.1 CP5.1 DP4.K LP2.2 P11.11 Q4.1 Q4.2 Q4.3 Q6.5 Q6.6 Q6.7 Q6.8 R100.1 R118.2 UP2.5 UP3.4 | length 56.3
  Top Layer w0.305: R118.2@162.154,29.564 162.154,30.531 162.89,31.267 166.903,31.267 167.818,30.353 v2(186.969,30.353)
  Top Layer w0.508: Q4.1@234.809,41.418 235.52,41.418 235.571,41.468 235.571,41.494 237.984,43.907 238.517,43.907 238.898,44.288 238.936,44.288 239.127,44.478 R100.1@239.127,44.516
  Bottom Layer w0.305: v2(186.969,30.353) 187.477,29.845 189.789,29.845 194.107,34.163 196.875,34.163 203.048,27.991 206.604,27.991
  other v1: 227.209,24.067 227.819,24.067 227.209,24.677 227.819,24.677 227.209,25.286 227.819,25.286 207.021,26.889 207.631,26.889 207.021,27.498 207.631,27.498 207.021,28.108 207.631,28.108 232.594,39.79 233.204,39.79 232.594,40.399 233.204,40.399 232.594,41.009 233.204,41.009 217.593,74.032 218.26,74.032 217.593,74.699 218.26,74.699 217.593,75.365 218.26,75.365 217.593,76.032 218.26,76.032 223.277,97.678 223.887,97.678 224.496,97.678 223.277,98.287 223.887,98.287 224.496,98.287
IRQ3: P5.49 P8.39 P9.39 U1.152 U12.37 UN1.3 | length 341
  Top Layer w0.203: v1(32.218,105.553) 32.209,105.562 32.209,108.345 U12.37@32.201,108.354 32.201,110.107 47.351,125.257 80.955,125.257 82.307,126.609 82.307,132.717 83.19,133.6 P5.49@83.19,133.9 ; UN1.3@39.026,42 44.307,42 v1@48.575,46.268 ; v1(47.041,20.98) 47.075,21.014 61.553,21.014 62.789,22.25 77.851,22.25 78.994,23.393 104.851,23.393 107.061,25.603 141.326,25.603 148.946,33.223 158.267,33.223 v1(158.928,33.884) ; U1.152@173.805,74.206 173.805,72.78 175.068,71.517 v1(175.068,71.466)
  Bottom Layer w0.203: v1(32.218,105.553) 33.311,104.46 33.311,74.082 50.368,57.024 50.368,51.181 48.616,49.428 v1(48.616,46.228) 48.652,46.191 48.652,32.834 48.655,32.831 48.655,31.993 48.26,31.598 48.26,29.896 47.041,28.677 v1(47.041,20.98) ; v1(158.928,33.884) 160.68,35.636 164.287,35.636 169.686,41.035 169.686,44.936 170.5,45.75 P9.39@170.5,46 ; P9.39@170.384,46.116 170.384,46.865 169.709,47.541 169.709,48.403 169.695,48.417 169.695,49.583 169.709,49.597 169.709,49.773 P8.39@170.5,50.564 ; P8.39@170.5,51 170.5,53.196 175.136,57.832 175.136,71.245 175.126,71.255 175.126,71.407 v1(175.068,71.466)
IRQ4: P5.47 P8.45 P9.45 U1.151 U12.38 UN1.2 | length 334
  Top Layer w0.203: v1(31.533,106.137) 31.551,106.155 U12.38@31.551,108.354 31.551,110.193 46.995,125.638 78.974,125.638 80.301,126.965 80.301,132.983 80.65,133.332 P5.47@80.65,133.9 ; UN1.2@39.026,41.35 44.47,41.35 48.043,44.923 v1(48.093,44.923) ; v1(48.096,32.599) 48.096,32.682 48.23,32.815 48.23,32.85 49.619,34.239 50.571,34.239 53.162,36.83 54.458,36.83 56.632,39.005 67.859,39.005 68.225,39.37 118.467,39.37 121.753,36.084 125.46,36.084 129.921,31.623 139.494,31.623 146.876,39.005 v1@163.333,39.005 ; v1(170.699,79.67) 170.725,79.67 173.366,77.029 173.366,75.293 173.323,75.25 173.323,74.224 U1.151@173.305,74.206
  Bottom Layer w0.203: v1(31.533,106.137) 31.533,104.384 31.761,104.156 31.761,74.285 49.53,56.516 49.53,52.451 48.057,50.978 48.057,45.78 48.093,45.743 v1(48.093,44.923) v1(48.093,44.923) 48.095,32.601 v1(48.096,32.599) ; v1(163.333,39.03) 163.333,44.389 164.5,45.556 P9.45@164.5,46 164.384,46.116 164.384,46.865 163.558,47.691 163.558,49.622 P8.45@164.5,50.564 ; P8.45@164.5,51 164.5,52.44 166.651,54.59 166.651,68.52 169.495,71.365 169.495,75.777 170.699,76.981 v1(170.699,79.67)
